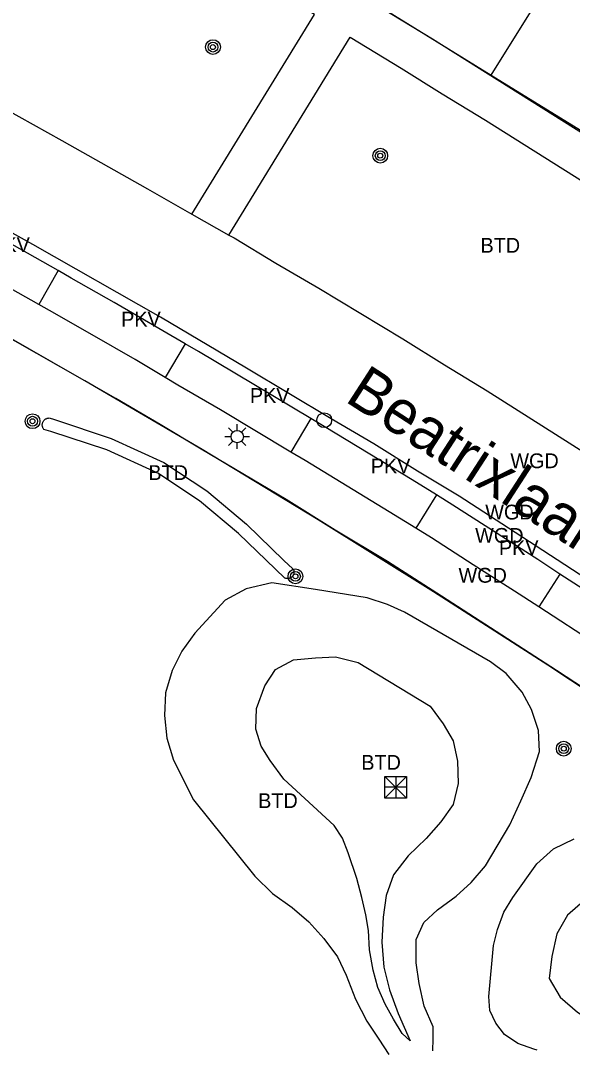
# Model space of a CAD drawing. Extents: x 198240 to 198429, y 356553 to 356721.
# Drawn here: x 198326.68 to 198349.04, y 356639.08 to 356680.75 of the extents above; entities that cross this region are included whole.
import ezdxf

# ---------------------------------------------------------------- set-up
doc = ezdxf.new("R2010")
doc.units = 0
for name, color, linetype in [('begroeid terreindeel kenmerkpunt', 7, 'Continuous'), ('BOOM', 7, 'Continuous'), ('grens individueel parkeervak', 7, 'Continuous'), ('Grens maaiveld', 7, 'Continuous'), ('identificerend kenmerkpunt parkeervak', 7, 'Continuous'), ('kant verharding', 7, 'Continuous'), ('kolk', 7, 'Continuous'), ('LICHTMAST', 7, 'Continuous'), ('openbare ruimte label tekst', 7, 'Continuous'), ('perceelsgrens_definitief', 7, 'Continuous'), ('Speelvoorziening', 7, 'Continuous'), ('wegdeel kenmerkpunt', 7, 'Continuous'), ('weginrichtingselement lijn', 7, 'Continuous')]:
    doc.layers.add(name, color=color, linetype=linetype)

msp = doc.modelspace()

# ---------------------------------------------------------------- linework, layer by layer
at = {"layer": 'BOOM'}
for centre, radius in [((198334.473, 356679.677), 0.3), ((198334.473, 356679.677), 0.2), ((198334.473, 356679.677), 0.1), ((198341.255, 356675.273), 0.3), ((198341.255, 356675.273), 0.2), ((198341.255, 356675.273), 0.1), ((198327.161, 356664.507), 0.3), ((198327.161, 356664.507), 0.2), ((198327.161, 356664.507), 0.1), ((198337.817, 356658.216), 0.3), ((198337.817, 356658.216), 0.2), ((198337.817, 356658.216), 0.1), ((198348.692, 356651.232), 0.3), ((198348.692, 356651.232), 0.2), ((198348.692, 356651.232), 0.1)]:
    msp.add_circle(centre, radius, dxfattribs=at)
at = {"layer": 'grens individueel parkeervak'}
for p, q in [((198328.199, 356670.612), (198327.419, 356669.24)), ((198333.343, 356667.649), (198332.543, 356666.276)), ((198338.445, 356664.616), (198337.634, 356663.255)), ((198343.53, 356661.52), (198342.69, 356660.174)), ((198348.537, 356658.312), (198347.676, 356656.983))]:
    msp.add_line(p, q, dxfattribs=at)
at = {"layer": 'Grens maaiveld'}
for points in [[(198372.981, 356641.75), (198367.706, 356645.661), (198366.187, 356646.802), (198364.538, 356647.958), (198362.833, 356649.176), (198361.195, 356650.33), (198359.548, 356651.463), (198357.799, 356652.691), (198352.878, 356655.977), (198347.848, 356659.26), (198346.187, 356660.353), (198344.459, 356661.463), (198342.759, 356662.483), (198340.988, 356663.592), (198339.269, 356664.603), (198335.834, 356666.664), (198332.346, 356668.725), (198327.175, 356671.678), (198323.573, 356673.677), (198320.05, 356675.592), (198317.553, 356676.932)], [(198327.592, 356664.494), (198327.604, 356664.515), (198327.619, 356664.535), (198327.635, 356664.553), (198327.652, 356664.569), (198327.671, 356664.585), (198327.691, 356664.598), (198327.713, 356664.61), (198327.735, 356664.619), (198327.758, 356664.627), (198327.781, 356664.633), (198327.805, 356664.637), (198327.829, 356664.638), (198328.057, 356664.571), (198330.35, 356663.812), (198332.487, 356662.837), (198334.226, 356661.679), (198335.838, 356660.333), (198337.351, 356658.864), (198337.718, 356658.523), (198337.729, 356658.504), (198337.738, 356658.483), (198337.746, 356658.462), (198337.751, 356658.441), (198337.755, 356658.419), (198337.757, 356658.397), (198337.757, 356658.374), (198337.756, 356658.352), (198337.752, 356658.33), (198337.746, 356658.309), (198337.739, 356658.287), (198337.73, 356658.267), (198337.719, 356658.248), (198337.706, 356658.229), (198337.692, 356658.212), (198337.677, 356658.196), (198337.66, 356658.181), (198337.642, 356658.168), (198337.623, 356658.156), (198337.603, 356658.146), (198337.582, 356658.138), (198337.561, 356658.132), (198337.539, 356658.127), (198337.517, 356658.125), (198337.495, 356658.124), (198337.472, 356658.125), (198337.45, 356658.128), (198337.428, 356658.133), (198337.407, 356658.14), (198337.386, 356658.148), (198337.007, 356658.502), (198335.504, 356659.961), (198333.926, 356661.277), (198332.243, 356662.399), (198330.168, 356663.346), (198327.907, 356664.093), (198327.623, 356664.177), (198327.609, 356664.196), (198327.595, 356664.216), (198327.584, 356664.238), (198327.574, 356664.26), (198327.567, 356664.283), (198327.561, 356664.307), (198327.558, 356664.331), (198327.557, 356664.355), (198327.557, 356664.379), (198327.56, 356664.403), (198327.565, 356664.427), (198327.572, 356664.45), (198327.581, 356664.473), (198327.592, 356664.494)], [(198343.389, 356638.974), (198343.402, 356639.466), (198343.401, 356639.948), (198343.03, 356640.791), (198342.826, 356641.71), (198342.71, 356642.552), (198342.715, 356643.499), (198343.015, 356644.182), (198343.576, 356644.698), (198344.337, 356645.248), (198344.941, 356645.803), (198345.516, 356646.474), (198346.502, 356648.141), (198346.953, 356649.116), (198347.37, 356650.067), (198347.707, 356651.12), (198347.67, 356651.972), (198347.389, 356652.823), (198347.01, 356653.528), (198346.352, 356654.273), (198345.722, 356654.753), (198342.233, 356656.77), (198341.548, 356657.071), (198340.73, 356657.344), (198338.625, 356657.679), (198336.86, 356657.96), (198335.814, 356657.718)], [(198335.814, 356657.718), (198334.969, 356657.249), (198333.734, 356655.907), (198333.219, 356655.178), (198332.825, 356654.405), (198332.55, 356653.498), (198332.507, 356652.579), (198332.603, 356651.657), (198332.869, 356650.759), (198333.683, 356649.152), (198336.17, 356646.057), (198336.882, 356645.355), (198337.678, 356644.792), (198338.362, 356644.207), (198338.962, 356643.538), (198339.52, 356642.791), (198339.87, 356642.044), (198340.247, 356641.073), (198340.706, 356640.183), (198341.203, 356639.447), (198341.598, 356638.833)], [(198347.617, 356639.006), (198347.475, 356639.042), (198346.828, 356639.275), (198346.287, 356639.639), (198345.935, 356640.096), (198345.691, 356640.614), (198345.65, 356641.176), (198345.843, 356643.252), (198346.007, 356643.901), (198346.27, 356644.596), (198346.627, 356645.198), (198347.603, 356646.563), (198348.274, 356647.167), (198349.119, 356647.571)], [(198355.423, 356642.194), (198355.328, 356642.451), (198354.846, 356643.261), (198354.393, 356643.982), (198353.807, 356644.635), (198353.149, 356645.122), (198352.227, 356645.566), (198351.429, 356645.638), (198350.422, 356645.527), (198349.57, 356645.114), (198348.838, 356644.484), (198348.416, 356643.729), (198348.214, 356642.804), (198348.101, 356641.911), (198348.543, 356641.156), (198349.256, 356640.546), (198350.809, 356639.574), (198351.421, 356638.896)]]:
    msp.add_lwpolyline(points, dxfattribs=at)
at = {"layer": 'kant verharding'}
msp.add_line((198333.616, 356672.898), (198335.12, 356672.056), dxfattribs=at)
for points in [[(198325.044, 356691.174), (198339.161, 356682.588), (198341.279, 356681.288), (198343.379, 356680.014), (198351.339, 356675.001), (198352.823, 356674.056), (198356.526, 356671.657), (198358.554, 356670.367), (198359.064, 356670.025)], [(198333.616, 356672.898), (198338.593, 356680.997), (198324.168, 356689.714)], [(198319.532, 356680.702), (198323.087, 356678.797), (198326.611, 356676.862), (198328.348, 356675.892), (198331.824, 356673.931), (198333.616, 356672.898)], [(198335.12, 356672.056), (198340.038, 356680.08), (198342.098, 356678.821), (198343.768, 356677.785), (198345.52, 356676.719), (198349.498, 356674.217), (198351.562, 356672.893), (198353.696, 356671.479), (198355.61, 356670.236)], [(198352.51, 356651.714), (198350.276, 356653.164), (198348.4, 356654.399), (198343.742, 356657.419), (198341.543, 356658.825), (198339.43, 356660.09), (198337.442, 356661.338), (198333.99, 356663.38), (198332.34, 356664.377), (198330.533, 356665.43), (198328.787, 356666.422), (198324.464, 356668.899), (198322.677, 356669.861), (198318.431, 356672.186), (198316.529, 356673.188), (198314.814, 356674.063)], [(198328.199, 356670.612), (198325.17, 356672.32), (198323.004, 356673.505)], [(198327.419, 356669.24), (198324.358, 356670.953), (198322.598, 356671.918), (198322.242, 356672.111)], [(198335.12, 356672.056), (198335.329, 356671.939), (198337.026, 356670.919), (198338.761, 356669.905), (198342.174, 356667.852), (198343.856, 356666.8), (198345.587, 356665.739), (198350.163, 356662.829)], [(198333.343, 356667.649), (198330.47, 356669.323), (198328.728, 356670.314), (198328.199, 356670.612)], [(198332.543, 356666.276), (198331.316, 356667.012), (198329.572, 356668.004), (198327.849, 356668.999), (198327.419, 356669.24)], [(198338.445, 356664.616), (198333.884, 356667.334), (198333.343, 356667.649)], [(198337.634, 356663.255), (198334.775, 356664.965), (198333.047, 356665.974), (198332.543, 356666.276)], [(198343.53, 356661.52), (198342.549, 356662.132), (198339.048, 356664.257), (198338.445, 356664.616)], [(198342.69, 356660.174), (198341.621, 356660.837), (198338.211, 356662.91), (198337.634, 356663.255)], [(198348.537, 356658.312), (198347.636, 356658.895), (198344.203, 356661.1), (198343.53, 356661.52)], [(198347.676, 356656.983), (198346.697, 356657.618), (198345.015, 356658.688), (198343.337, 356659.773), (198342.69, 356660.174)], [(198353.497, 356655.053), (198352.664, 356655.604), (198351.039, 356656.691), (198348.537, 356658.312)], [(198352.624, 356653.732), (198351.715, 356654.33), (198350.052, 356655.44), (198347.676, 356656.983)], [(198342.463, 356639.381), (198342.145, 356639.678), (198341.793, 356640.267), (198341.448, 356640.868), (198341.156, 356641.553), (198340.964, 356642.248), (198340.82, 356643.073), (198340.776, 356643.853), (198340.664, 356644.489), (198340.512, 356645.197), (198340.309, 356645.963), (198339.949, 356647.008), (198339.723, 356647.597), (198339.393, 356648.115), (198337.346, 356649.999), (198336.786, 356650.749), (198336.429, 356651.337), (198336.212, 356652.018), (198336.235, 356652.861), (198336.58, 356653.775), (198337.01, 356654.436), (198337.736, 356654.829), (198338.627, 356654.918), (198339.446, 356654.95), (198340.362, 356654.725), (198343.271, 356652.948), (198343.808, 356652.242), (198344.214, 356651.548), (198344.384, 356650.729), (198344.418, 356649.816), (198344.205, 356648.97), (198343.715, 356648.269), (198343.112, 356647.587), (198342.38, 356646.892), (198341.791, 356646.12), (198341.495, 356645.272), (198341.37, 356644.392), (198341.312, 356643.391), (198341.401, 356642.371), (198341.625, 356641.458), (198341.974, 356640.491), (198342.463, 356639.381)]]:
    msp.add_lwpolyline(points, dxfattribs=at)
at = {"layer": 'kolk'}
msp.add_circle((198338.984, 356664.549), 0.3, dxfattribs=at)
at = {"layer": 'LICHTMAST'}
for p, q in [((198335.281, 356664.059), (198335.104, 356664.236)), ((198335.458, 356664.132), (198335.458, 356664.382)), ((198335.635, 356664.059), (198335.812, 356664.236)), ((198334.958, 356663.882), (198335.208, 356663.882)), ((198335.708, 356663.882), (198335.958, 356663.882)), ((198335.104, 356663.528), (198335.281, 356663.705)), ((198335.458, 356663.382), (198335.458, 356663.632)), ((198335.812, 356663.528), (198335.635, 356663.705))]:
    msp.add_line(p, q, dxfattribs=at)
msp.add_circle((198335.458, 356663.882), 0.25, dxfattribs=at)
at = {"layer": 'perceelsgrens_definitief'}
for points in [[(198345.747, 356678.545), (198365.905, 356710.845)], [(198340.281, 356681.925), (198345.747, 356678.545)], [(198345.747, 356678.545), (198347.687, 356677.346)], [(198347.687, 356677.346), (198351.308, 356675.119)], [(198370.586, 356638.823), (198366.164, 356642.103), (198361.698, 356645.323), (198357.189, 356648.483), (198352.638, 356651.581), (198348.046, 356654.619), (198343.413, 356657.594), (198338.741, 356660.506), (198334.03, 356663.356), (198329.281, 356666.142), (198324.495, 356668.863), (198319.673, 356671.52), (198314.815, 356674.112)]]:
    msp.add_lwpolyline(points, dxfattribs=at)
at = {"layer": 'Speelvoorziening'}
for p, q in [((198341.445, 356650.108), (198342.325, 356650.108)), ((198341.445, 356649.228), (198341.445, 356650.108)), ((198341.445, 356650.108), (198342.325, 356649.228)), ((198341.445, 356649.228), (198342.325, 356650.108)), ((198341.885, 356650.108), (198341.885, 356649.228)), ((198342.325, 356650.108), (198342.325, 356649.228)), ((198342.325, 356649.668), (198341.445, 356649.668)), ((198342.325, 356649.228), (198341.445, 356649.228))]:
    msp.add_line(p, q, dxfattribs=at)
at = {"layer": 'weginrichtingselement lijn'}
msp.add_lwpolyline([(198372.981, 356641.75), (198367.706, 356645.661), (198366.187, 356646.802), (198364.538, 356647.958), (198362.833, 356649.176), (198361.195, 356650.33), (198359.548, 356651.463), (198357.799, 356652.691), (198352.878, 356655.977), (198347.848, 356659.26), (198346.187, 356660.353), (198344.459, 356661.463), (198342.759, 356662.483), (198340.988, 356663.592), (198339.269, 356664.603), (198335.834, 356666.664), (198332.346, 356668.725), (198327.175, 356671.678), (198323.573, 356673.677), (198320.05, 356675.592), (198317.553, 356676.932)], dxfattribs=at)

# ---------------------------------------------------------------- texts
at = {"layer": 'begroeid terreindeel kenmerkpunt'}
for p in [(198345.319, 356671.34), (198331.856, 356662.124), (198340.486, 356650.376), (198336.307, 356648.821)]:
    msp.add_text('BTD', height=0.6, dxfattribs=at).set_placement(p)
at = {"layer": 'identificerend kenmerkpunt parkeervak'}
for p in [(198325.447, 356671.362), (198330.752, 356668.345), (198335.971, 356665.248), (198340.871, 356662.393), (198346.066, 356659.084)]:
    msp.add_text('PKV', height=0.6, dxfattribs=at).set_placement(p)
at = {"layer": 'openbare ruimte label tekst'}
msp.add_text('Beatrixlaan', height=1.8, rotation=327.1, dxfattribs=at).set_placement((198339.771, 356665.343))
at = {"layer": 'wegdeel kenmerkpunt'}
for p in [(198346.528, 356662.603), (198345.511, 356660.523), (198345.102, 356659.577), (198344.426, 356657.96)]:
    msp.add_text('WGD', height=0.6, dxfattribs=at).set_placement(p)

doc.saveas('drawing.dxf')
